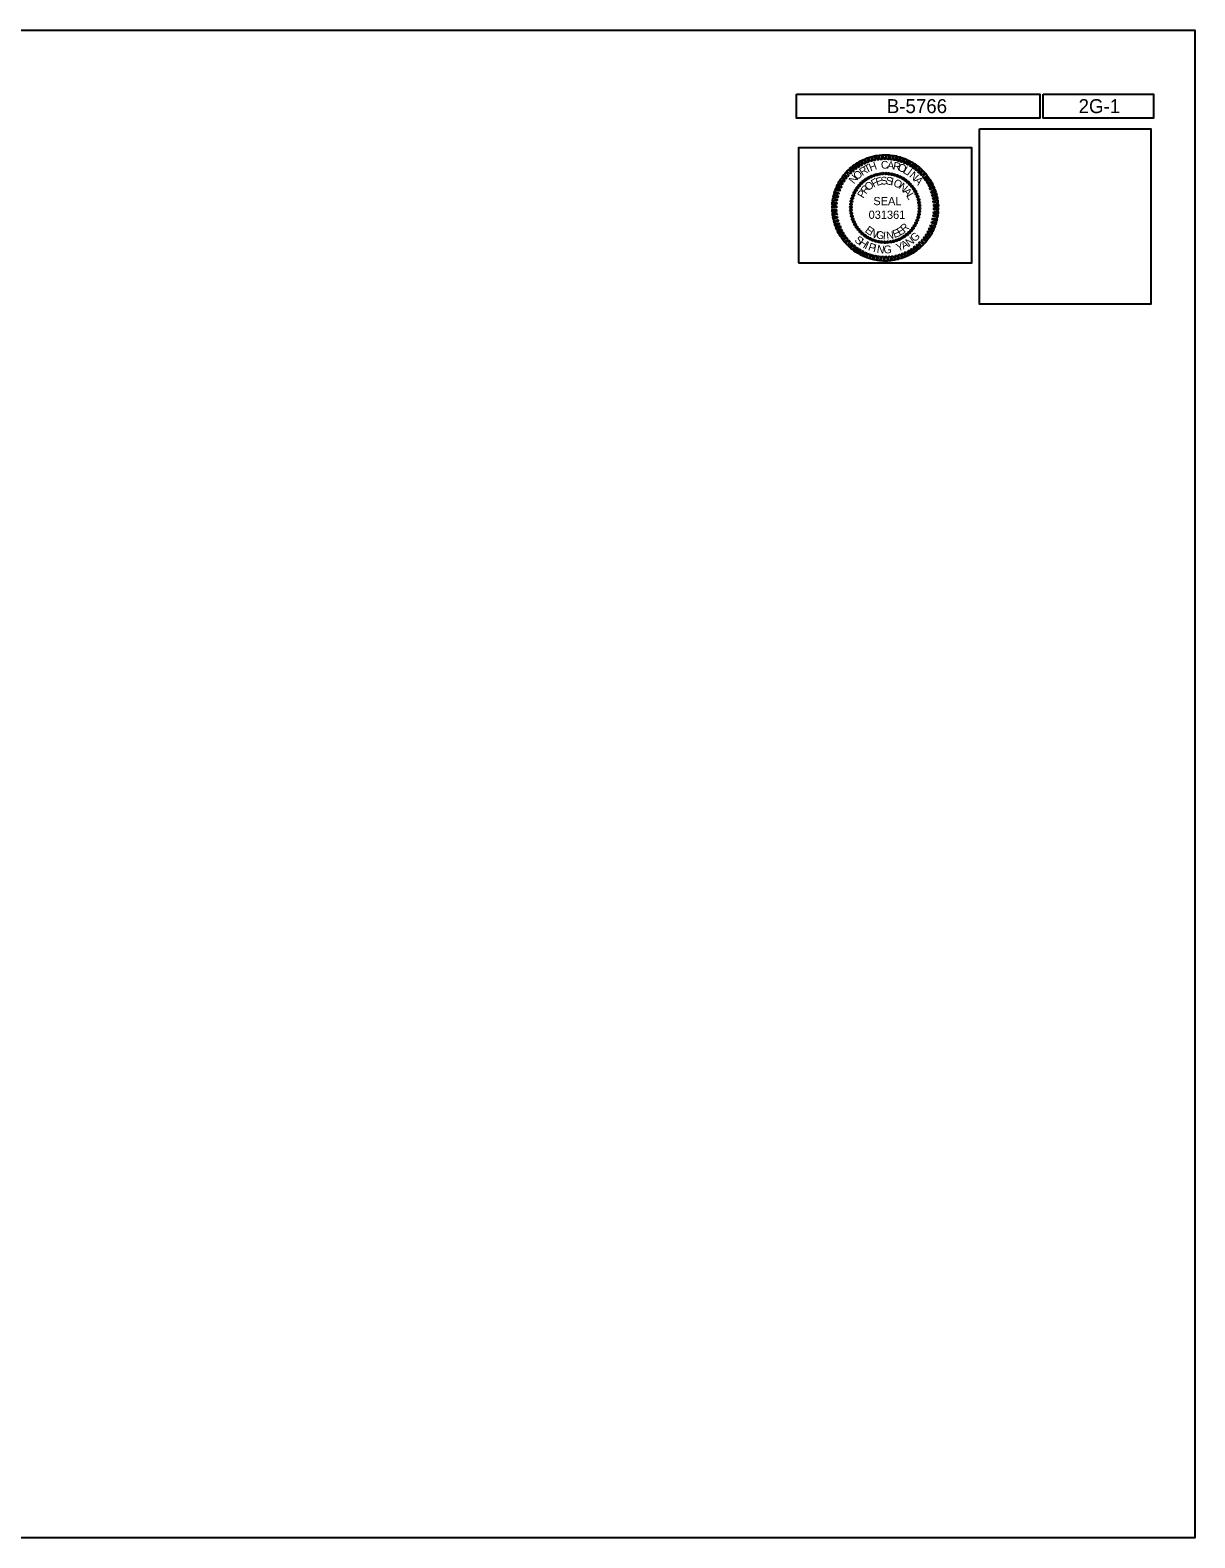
# Model space of a CAD drawing. Extents: x 0 to 7.42, y -0.92 to 0.
# Drawn here: x 0.708 to 1.417, y -0.917 to 0 of the extents above; entities that cross this region are included whole.
import ezdxf

# ---------------------------------------------------------------- set-up
doc = ezdxf.new("R2010")
doc.units = 0
for name, color, linetype in [('Prop Dimension', 7, 'Continuous'), ('Prop DSN Text', 7, 'Continuous'), ('Scratch_Level_1', 7, 'Continuous'), ('Sheet Plot Border Inside CELL', 7, 'Continuous')]:
    doc.layers.add(name, color=color, linetype=linetype)

msp = doc.modelspace()

# ---------------------------------------------------------------- linework, layer by layer
at = {"layer": 'Prop Dimension'}
for p, q in [((1.21662, -0.09076), (1.21662, -0.09076)), ((1.21821, -0.0898), (1.21821, -0.0898)), ((1.21984, -0.08896), (1.21984, -0.08896)), ((1.2215, -0.0883), (1.2215, -0.0883)), ((1.22325, -0.0878), (1.22325, -0.0878)), ((1.22508, -0.08746), (1.22508, -0.08746)), ((1.22687, -0.08721), (1.22687, -0.08721)), ((1.2287, -0.08718), (1.2287, -0.08718)), ((1.23054, -0.0873), (1.23054, -0.0873)), ((1.23233, -0.08759), (1.23233, -0.08759)), ((1.23408, -0.08796), (1.23408, -0.08796)), ((1.23583, -0.08855), (1.23583, -0.08855)), ((1.2375, -0.0893), (1.2375, -0.0893)), ((1.23912, -0.09013), (1.23912, -0.09013)), ((1.24062, -0.09118), (1.24062, -0.09118)), ((1.20879, -0.10059), (1.20879, -0.10059)), ((1.20954, -0.09892), (1.20954, -0.09892)), ((1.21038, -0.09729), (1.21038, -0.09729)), ((1.21142, -0.09579), (1.21142, -0.09579)), ((1.21254, -0.09434), (1.21254, -0.09434)), ((1.21379, -0.09305), (1.21379, -0.09305)), ((1.21517, -0.0918), (1.21517, -0.0918)), ((1.24208, -0.0923), (1.24208, -0.0923)), ((1.24337, -0.09355), (1.24337, -0.09355)), ((1.24462, -0.09492), (1.24462, -0.09492)), ((1.24566, -0.09638), (1.24566, -0.09638)), ((1.24662, -0.09796), (1.24662, -0.09796)), ((1.24745, -0.09959), (1.24745, -0.09959)), ((1.20742, -0.10771), (1.20742, -0.10771)), ((1.20746, -0.10954), (1.20746, -0.10954)), ((1.20754, -0.10588), (1.20754, -0.10588)), ((1.20784, -0.10409), (1.20784, -0.10409)), ((1.20821, -0.10234), (1.20821, -0.10234)), ((1.22833, -0.10809), (1.22833, -0.10809)), ((1.24811, -0.10126), (1.24811, -0.10126)), ((1.24861, -0.10301), (1.24861, -0.10301)), ((1.24895, -0.10484), (1.24895, -0.10484)), ((1.2492, -0.10663), (1.2492, -0.10663)), ((1.24924, -0.10846), (1.24924, -0.10846)), ((1.20771, -0.11134), (1.20771, -0.11134)), ((1.20804, -0.11317), (1.20804, -0.11317)), ((1.20854, -0.11492), (1.20854, -0.11492)), ((1.20921, -0.11659), (1.20921, -0.11659)), ((1.21004, -0.11821), (1.21004, -0.11821)), ((1.24628, -0.11887), (1.24628, -0.11887)), ((1.24712, -0.11725), (1.24712, -0.11725)), ((1.24786, -0.11559), (1.24786, -0.11559)), ((1.24845, -0.11384), (1.24845, -0.11384)), ((1.24883, -0.11209), (1.24883, -0.11209)), ((1.24911, -0.11029), (1.24911, -0.11029)), ((1.211, -0.11979), (1.211, -0.11979)), ((1.21204, -0.12125), (1.21204, -0.12125)), ((1.21329, -0.12262), (1.21329, -0.12262)), ((1.21459, -0.12387), (1.21459, -0.12387)), ((1.21604, -0.125), (1.21604, -0.125)), ((1.21754, -0.12604), (1.21754, -0.12604)), ((1.21917, -0.12687), (1.21917, -0.12687)), ((1.22084, -0.12762), (1.22084, -0.12762)), ((1.22258, -0.1282), (1.22258, -0.1282)), ((1.23516, -0.12787), (1.23516, -0.12787)), ((1.23683, -0.1272), (1.23683, -0.1272)), ((1.23845, -0.12637), (1.23845, -0.12637)), ((1.24003, -0.12542), (1.24003, -0.12542)), ((1.2415, -0.12437), (1.2415, -0.12437)), ((1.24287, -0.12312), (1.24287, -0.12312)), ((1.24412, -0.12183), (1.24412, -0.12183)), ((1.24525, -0.12037), (1.24525, -0.12037)), ((1.22433, -0.12858), (1.22433, -0.12858)), ((1.22612, -0.12887), (1.22612, -0.12887)), ((1.22795, -0.129), (1.22795, -0.129)), ((1.22979, -0.12895), (1.22979, -0.12895)), ((1.23158, -0.1287), (1.23158, -0.1287)), ((1.23342, -0.12837), (1.23342, -0.12837))]:
    msp.add_line(p, q, dxfattribs=at)
for points in [[(1.21017, -0.08476), (1.20838, -0.08276), (1.20951, -0.08188), (1.21096, -0.08421)], [(1.21175, -0.08351), (1.21021, -0.08138), (1.21129, -0.0806), (1.21267, -0.08301)], [(1.21359, -0.08247), (1.21204, -0.08022), (1.21334, -0.07955), (1.21437, -0.08197)], [(1.21537, -0.08147), (1.21404, -0.07913), (1.21534, -0.07855), (1.21629, -0.0811)], [(1.21721, -0.0806), (1.21612, -0.07818), (1.21737, -0.07768), (1.21825, -0.08035)], [(1.21925, -0.07993), (1.21829, -0.07743), (1.21959, -0.07705), (1.22012, -0.07963)], [(1.22125, -0.07938), (1.22037, -0.07676), (1.22179, -0.07647), (1.22212, -0.07918)], [(1.22325, -0.07893), (1.22258, -0.07626), (1.22395, -0.07613), (1.22425, -0.0788)], [(1.22525, -0.07868), (1.22479, -0.07601), (1.2262, -0.07585), (1.22625, -0.07855)], [(1.22733, -0.07847), (1.22712, -0.07576), (1.2285, -0.0758), (1.22833, -0.07851)], [(1.22933, -0.07851), (1.22933, -0.0758), (1.2307, -0.07585), (1.23033, -0.07855)], [(1.23142, -0.07863), (1.23158, -0.07593), (1.23295, -0.07618), (1.23242, -0.0788)], [(1.23342, -0.07897), (1.23379, -0.0763), (1.23516, -0.07651), (1.23442, -0.0791)], [(1.23554, -0.07943), (1.23595, -0.07672), (1.23737, -0.07705), (1.23641, -0.07963)], [(1.23753, -0.07997), (1.23816, -0.07738), (1.23945, -0.0778), (1.23841, -0.08026)], [(1.23941, -0.08072), (1.24037, -0.0781), (1.24153, -0.0786), (1.24037, -0.08101)], [(1.24128, -0.08151), (1.24233, -0.07905), (1.24362, -0.07963), (1.2422, -0.08197)], [(1.2432, -0.08247), (1.24433, -0.0801), (1.24558, -0.0808), (1.244, -0.08297)], [(1.24483, -0.08359), (1.24628, -0.08118), (1.24737, -0.08205), (1.24575, -0.08409)], [(1.20317, -0.09234), (1.20084, -0.09109), (1.20167, -0.08993), (1.20384, -0.09159)], [(1.20442, -0.09068), (1.20217, -0.08926), (1.20296, -0.08805), (1.20496, -0.08988)], [(1.20567, -0.08909), (1.20351, -0.08746), (1.20442, -0.08638), (1.20626, -0.08834)], [(1.20713, -0.08751), (1.20501, -0.0858), (1.20604, -0.08484), (1.20779, -0.08684)], [(1.20851, -0.08605), (1.20667, -0.08421), (1.20767, -0.08322), (1.20929, -0.08546)], [(1.24653, -0.08484), (1.24808, -0.08255), (1.24916, -0.08347), (1.24733, -0.08543)], [(1.24811, -0.08613), (1.24983, -0.08396), (1.25083, -0.08496), (1.24891, -0.08676)], [(1.24961, -0.08759), (1.25141, -0.08563), (1.25241, -0.08663), (1.25024, -0.08826)], [(1.25108, -0.08909), (1.25299, -0.08721), (1.25386, -0.08834), (1.25166, -0.08993)], [(1.25233, -0.09071), (1.25436, -0.08896), (1.25516, -0.09018), (1.25283, -0.09151)], [(1.25341, -0.09243), (1.25561, -0.09084), (1.25641, -0.09209), (1.25399, -0.09326)], [(1.19934, -0.10188), (1.19676, -0.10154), (1.19705, -0.10013), (1.19967, -0.10101)], [(1.19988, -0.09988), (1.1973, -0.09934), (1.19759, -0.09796), (1.20021, -0.09901)], [(1.20051, -0.09788), (1.19793, -0.09713), (1.19846, -0.09584), (1.20096, -0.09701)], [(1.20134, -0.09604), (1.19876, -0.09509), (1.19938, -0.0938), (1.20176, -0.09513)], [(1.20217, -0.09413), (1.1998, -0.09309), (1.20042, -0.0918), (1.20267, -0.09334)], [(1.25449, -0.09426), (1.25683, -0.0928), (1.25736, -0.09409), (1.25499, -0.09505)], [(1.25533, -0.09604), (1.25778, -0.0948), (1.25833, -0.09613), (1.25574, -0.09696)], [(1.25608, -0.09801), (1.25861, -0.09692), (1.25907, -0.09821), (1.25649, -0.09888)], [(1.25674, -0.10001), (1.25941, -0.09904), (1.25966, -0.10042), (1.25703, -0.10088)], [(1.1988, -0.11017), (1.19609, -0.1105), (1.19601, -0.10909), (1.19871, -0.10917)], [(1.19876, -0.10809), (1.19605, -0.10821), (1.19605, -0.10679), (1.19876, -0.10709)], [(1.1988, -0.10601), (1.19609, -0.10592), (1.19618, -0.10454), (1.19888, -0.10501)], [(1.19901, -0.10401), (1.19634, -0.10376), (1.19651, -0.10234), (1.19921, -0.10301)], [(1.25724, -0.10201), (1.25986, -0.10121), (1.26011, -0.10263), (1.25749, -0.10288)], [(1.25761, -0.10401), (1.26032, -0.10342), (1.26044, -0.10484), (1.25778, -0.10501)], [(1.25786, -0.10601), (1.26057, -0.10567), (1.26066, -0.10709), (1.25795, -0.107)], [(1.25791, -0.10809), (1.26061, -0.10796), (1.26061, -0.10937), (1.25791, -0.10909)], [(1.19905, -0.11217), (1.19634, -0.11275), (1.19621, -0.11134), (1.19888, -0.11117)], [(1.19942, -0.11417), (1.1968, -0.11496), (1.19655, -0.11354), (1.19917, -0.11329)], [(1.19992, -0.11617), (1.19726, -0.11712), (1.19701, -0.11575), (1.19963, -0.11529)], [(1.20059, -0.11817), (1.19805, -0.11925), (1.19759, -0.11796), (1.20017, -0.11729)], [(1.25616, -0.11829), (1.25874, -0.11904), (1.2582, -0.12033), (1.2557, -0.11917)], [(1.25678, -0.11629), (1.25936, -0.11684), (1.25907, -0.11821), (1.25645, -0.11717)], [(1.25733, -0.11429), (1.25991, -0.11462), (1.25961, -0.11604), (1.25699, -0.11517)], [(1.25766, -0.11217), (1.26032, -0.11242), (1.26016, -0.11384), (1.25745, -0.11317)], [(1.25786, -0.11017), (1.26057, -0.11025), (1.26049, -0.11162), (1.25778, -0.11117)], [(1.20134, -0.12012), (1.19888, -0.12137), (1.19834, -0.12004), (1.20092, -0.11921)], [(1.20217, -0.12192), (1.19984, -0.12337), (1.1993, -0.12208), (1.20167, -0.12112)], [(1.20326, -0.12375), (1.20104, -0.12533), (1.20026, -0.12408), (1.20267, -0.12292)], [(1.20434, -0.12545), (1.20229, -0.1272), (1.20151, -0.126), (1.20384, -0.12467)], [(1.20559, -0.12708), (1.20367, -0.12895), (1.20279, -0.12783), (1.20501, -0.12625)], [(1.20704, -0.12858), (1.20526, -0.13054), (1.20426, -0.12954), (1.20642, -0.12792)], [(1.25099, -0.12708), (1.25316, -0.1287), (1.25224, -0.12979), (1.25041, -0.12783)], [(1.25224, -0.1255), (1.25449, -0.12692), (1.2537, -0.12812), (1.2517, -0.12629)], [(1.25349, -0.12383), (1.25583, -0.12508), (1.25499, -0.12625), (1.25283, -0.12458)], [(1.25449, -0.12204), (1.25686, -0.12308), (1.25624, -0.12437), (1.25399, -0.12283)], [(1.25533, -0.12012), (1.25791, -0.12108), (1.25728, -0.12237), (1.25491, -0.12104)], [(1.20854, -0.13004), (1.20684, -0.1322), (1.20584, -0.1312), (1.20776, -0.12942)], [(1.21013, -0.13133), (1.20859, -0.13362), (1.20751, -0.1327), (1.20934, -0.13075)], [(1.21184, -0.13258), (1.21038, -0.135), (1.20929, -0.13412), (1.21092, -0.13208)], [(1.21346, -0.1337), (1.21234, -0.13608), (1.21109, -0.13537), (1.21267, -0.1332)], [(1.21537, -0.13466), (1.21434, -0.13712), (1.21304, -0.13653), (1.21446, -0.1342)], [(1.21725, -0.13545), (1.21629, -0.13808), (1.21512, -0.13758), (1.21629, -0.13516)], [(1.21912, -0.1362), (1.2185, -0.13878), (1.21721, -0.13837), (1.21825, -0.13591)], [(1.22112, -0.13675), (1.22071, -0.13945), (1.21929, -0.13912), (1.22025, -0.13653)], [(1.22325, -0.1372), (1.22287, -0.13987), (1.2215, -0.13966), (1.22225, -0.13708)], [(1.22525, -0.13753), (1.22508, -0.14025), (1.22371, -0.14), (1.22425, -0.13737)], [(1.23142, -0.1375), (1.23187, -0.14016), (1.23045, -0.14033), (1.23042, -0.13762)], [(1.23342, -0.13725), (1.23408, -0.13991), (1.2327, -0.14003), (1.23242, -0.13737)], [(1.23541, -0.13678), (1.23628, -0.13941), (1.23487, -0.1397), (1.23454, -0.137)], [(1.23741, -0.13625), (1.23837, -0.13875), (1.23708, -0.13912), (1.23653, -0.13653)], [(1.23945, -0.13558), (1.24053, -0.138), (1.23928, -0.1385), (1.23841, -0.13583)], [(1.24128, -0.1347), (1.24262, -0.13703), (1.24133, -0.13762), (1.24037, -0.13508)], [(1.24308, -0.1337), (1.24462, -0.13595), (1.24333, -0.13662), (1.24228, -0.1342)], [(1.24491, -0.13266), (1.24645, -0.13478), (1.24537, -0.13558), (1.244, -0.13316)], [(1.2465, -0.13141), (1.24828, -0.13341), (1.24716, -0.13428), (1.2457, -0.13195)], [(1.24816, -0.13012), (1.24999, -0.13195), (1.24899, -0.13295), (1.24737, -0.1307)], [(1.24953, -0.12867), (1.25166, -0.13037), (1.25061, -0.13133), (1.24886, -0.12933)], [(1.22733, -0.13766), (1.22733, -0.14037), (1.22595, -0.14033), (1.22633, -0.13762)], [(1.22933, -0.1377), (1.22954, -0.14041), (1.22817, -0.14037), (1.22833, -0.13766)]]:
    msp.add_lwpolyline(points, close=True, dxfattribs=at)
for centre, major_axis in [((1.21518, -0.09185), (-0.000377, 0.000466)), ((1.21665, -0.09076), (-0.000335, 0.000497)), ((1.2182, -0.08981), (-0.000291, 0.000525)), ((1.21984, -0.089), (-0.000244, 0.000548)), ((1.22153, -0.08833), (-0.000195, 0.000567)), ((1.22328, -0.08781), (-0.000145, 0.000582)), ((1.22507, -0.08745), (-0.000094, 0.000592)), ((1.22688, -0.08724), (-0.000042, 0.000598)), ((1.2287, -0.08719), (0.00001, 0.0006)), ((1.23052, -0.08731), (0.000063, 0.000597)), ((1.23232, -0.08757), (0.000114, 0.000589)), ((1.23409, -0.088), (0.000165, 0.000577)), ((1.23582, -0.08858), (0.000215, 0.00056)), ((1.23749, -0.08931), (0.000263, 0.000539)), ((1.2391, -0.09018), (0.000309, 0.000514)), ((1.24062, -0.09118), (0.000353, 0.000485)), ((1.24204, -0.09232), (0.000394, 0.000453)), ((1.20883, -0.1006), (-0.00056, 0.000215)), ((1.20955, -0.09893), (-0.000539, 0.000263)), ((1.21042, -0.09732), (-0.000514, 0.000309)), ((1.21143, -0.0958), (-0.000485, 0.000353)), ((1.21256, -0.09438), (-0.000453, 0.000394)), ((1.21382, -0.09306), (-0.000417, 0.000431)), ((1.24336, -0.09357), (0.000431, 0.000417)), ((1.24457, -0.09494), (0.000466, 0.000377)), ((1.24566, -0.0964), (0.000497, 0.000335)), ((1.24661, -0.09796), (0.000525, 0.000291)), ((1.24742, -0.09959), (0.000548, 0.000244)), ((1.24809, -0.10128), (0.000567, 0.000195)), ((1.20744, -0.10772), (-0.0006, 0.00001)), ((1.20749, -0.10954), (-0.000598, -0.000042)), ((1.20755, -0.1059), (-0.000597, 0.000063)), ((1.20782, -0.1041), (-0.000589, 0.000114)), ((1.20825, -0.10233), (-0.000577, 0.000165)), ((1.24861, -0.10303), (0.000582, 0.000145)), ((1.24897, -0.10482), (0.000592, 0.000094)), ((1.24911, -0.11027), (0.000597, -0.000063)), ((1.24918, -0.10663), (0.000598, 0.000042)), ((1.24922, -0.10845), (0.0006, -0.00001)), ((1.2077, -0.11135), (-0.000592, -0.000094)), ((1.20806, -0.11314), (-0.000582, -0.000145)), ((1.20858, -0.11489), (-0.000567, -0.000195)), ((1.20925, -0.11658), (-0.000548, -0.000244)), ((1.21006, -0.11821), (-0.000525, -0.000291)), ((1.21101, -0.11977), (-0.000497, -0.000335)), ((1.24624, -0.11885), (0.000514, -0.000309)), ((1.24711, -0.11724), (0.000539, -0.000263)), ((1.24784, -0.11557), (0.00056, -0.000215)), ((1.24842, -0.11384), (0.000577, -0.000165)), ((1.24884, -0.11207), (0.000589, -0.000114)), ((1.2121, -0.12123), (-0.000466, -0.000377)), ((1.2133, -0.1226), (-0.000431, -0.000417)), ((1.21463, -0.12385), (-0.000394, -0.000453)), ((1.21605, -0.12499), (-0.000353, -0.000485)), ((1.21757, -0.126), (-0.000309, -0.000514)), ((1.21917, -0.12686), (-0.000263, -0.000539)), ((1.22085, -0.12759), (-0.000215, -0.00056)), ((1.22257, -0.12817), (-0.000165, -0.000577)), ((1.22435, -0.1286), (-0.000114, -0.000589)), ((1.22615, -0.12886), (-0.000063, -0.000597)), ((1.22979, -0.12893), (0.000042, -0.000598)), ((1.2316, -0.12872), (0.000094, -0.000592)), ((1.23339, -0.12836), (0.000145, -0.000582)), ((1.23514, -0.12784), (0.000195, -0.000567)), ((1.23683, -0.12717), (0.000244, -0.000548)), ((1.23846, -0.12636), (0.000291, -0.000525)), ((1.24002, -0.12541), (0.000335, -0.000497)), ((1.24148, -0.12432), (0.000377, -0.000466)), ((1.24285, -0.12312), (0.000417, -0.000431)), ((1.2441, -0.12179), (0.000453, -0.000394)), ((1.24524, -0.12037), (0.000485, -0.000353)), ((1.22797, -0.12898), (-0.00001, -0.0006))]:
    msp.add_ellipse(centre, major_axis=major_axis, ratio=0.999708, dxfattribs=at)
at = {"layer": 'Scratch_Level_1'}
for points in [[(1.17438, -0.03888), (1.32246, -0.03888), (1.32246, -0.05353), (1.17438, -0.05353)], [(1.32446, -0.03888), (1.39143, -0.03888), (1.39143, -0.05353), (1.32446, -0.05353)], [(1.28562, -0.06), (1.38984, -0.06), (1.38984, -0.16659), (1.28562, -0.16659)], [(1.17558, -0.14141), (1.28094, -0.14141), (1.28094, -0.07145), (1.17558, -0.07145)]]:
    msp.add_lwpolyline(points, close=True, dxfattribs=at)
at = {"layer": 'Sheet Plot Border Inside CELL'}
msp.add_lwpolyline([(0, 0), (1.41667, 0), (1.41667, -0.91667), (0, -0.91667)], close=True, dxfattribs=at)

# ---------------------------------------------------------------- texts
at = {"layer": 'Prop Dimension'}
for s, height, rotation, p in [('T', 0.00471, 26.07029, (1.21693, -0.08712)), ('H', 0.00471, 19.82067, (1.21947, -0.08596)), ('C', 0.00471, 1.07179, (1.2258, -0.08425)), ('A', 0.00471, 354.82217, (1.22946, -0.08421)), ('R', 0.00471, 348.57255, (1.2328, -0.08459)), ('O', 0.00471, 342.32292, (1.23571, -0.08533)), ('N', 0.00471, 51.06879, (1.20935, -0.09383)), ('O', 0.00471, 38.56954, (1.21122, -0.09133)), ('R', 0.00471, 32.31991, (1.21443, -0.0887)), ('F', 0.00471, 29.29997, (1.22134, -0.09575)), ('E', 0.00471, 17.67092, (1.22338, -0.09475)), ('S', 0.00471, 6.18332, (1.2258, -0.09408)), ('S', 0.00471, 358.47777, (1.22876, -0.09395)), ('I', 0.00471, 350.09313, (1.23143, -0.09417)), ('O', 0.00471, 335.36112, (1.23288, -0.09445)), ('L', 0.00471, 329.82368, (1.23876, -0.08654)), ('I', 0.00471, 323.57405, (1.24109, -0.08775)), ('N', 0.00471, 317.32443, (1.24271, -0.08883)), ('A', 0.00471, 311.0748, (1.24559, -0.09154)), ('P', 0.00471, 60.12218, (1.2151, -0.10258)), ('R', 0.00471, 52.41663, (1.21663, -0.1)), ('O', 0.00471, 43.58747, (1.21838, -0.098)), ('N', 0.00471, 319.95002, (1.23613, -0.09592)), ('A', 0.00471, 312.24447, (1.23888, -0.09837)), ('L', 0.00471, 301.67519, (1.24096, -0.1007)), ('031361', 0.004999, 360, (1.21826, -0.11474)), ('SEAL', 0.004999, 360, (1.22113, -0.10641)), ('E', 0.00471, 323.67983, (1.21563, -0.12244)), ('R', 0.00471, 40.73534, (1.23992, -0.12332)), ('S', 0.0048, 320.12241, (1.2093, -0.12822)), ('H', 0.0048, 327.16047, (1.21191, -0.1304)), ('N', 0.00471, 331.38538, (1.21851, -0.12449)), ('G', 0.00471, 346.79648, (1.22246, -0.12632)), ('I', 0.00471, 355.04053, (1.2268, -0.12711)), ('N', 0.00471, 7.73408, (1.22934, -0.12728)), ('E', 0.00471, 20.04111, (1.23384, -0.12644)), ('E', 0.00471, 30.12137, (1.23713, -0.12516)), ('A', 0.0048, 26.97979, (1.23937, -0.1335)), ('N', 0.0048, 34.95898, (1.24279, -0.13173)), ('G', 0.0048, 44.1098, (1.24636, -0.12913)), ('I', 0.0048, 335.85032, (1.21547, -0.13263)), ('P', 0.0048, 340.69879, (1.21759, -0.13363)), ('I', 0.0048, 347.6024, (1.22074, -0.13473)), ('N', 0.0048, 352.45087, (1.22302, -0.13528)), ('G', 0.0048, 1.60169, (1.22741, -0.13578)), ('Y', 0.0048, 19.5768, (1.236, -0.13471))]:
    msp.add_text(s, height=height, rotation=rotation, dxfattribs=at).set_placement(p)
at = {"layer": 'Prop DSN Text'}
for s, p in [('B-5766', (1.22932, -0.05045)), ('2G-1', (1.34596, -0.05045))]:
    msp.add_text(s, height=0.0085, dxfattribs=at).set_placement(p)

doc.saveas('drawing.dxf')
